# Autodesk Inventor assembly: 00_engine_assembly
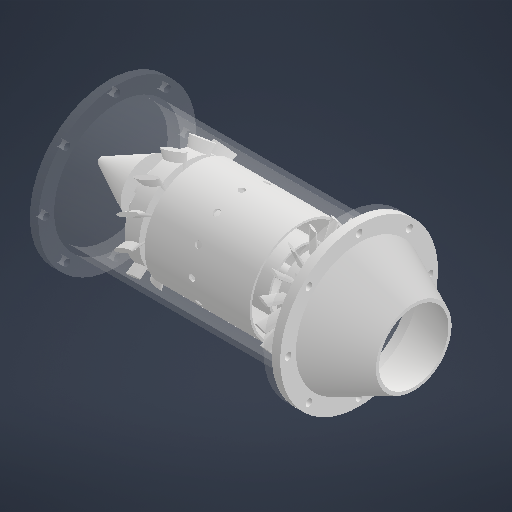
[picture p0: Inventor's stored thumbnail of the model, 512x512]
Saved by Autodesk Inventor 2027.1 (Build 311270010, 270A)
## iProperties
Created: 2026-10
Part Number: 00_engine_assembly
Document SubType Name: Assembly
Designer: BHAVAN KUMAR
Author: BHAVAN KUMAR
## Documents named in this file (8)
- C:\Users\BHAVAN KUMAR\OneDrive\00_engine_assembly.iam
- C:\Users\BHAVAN KUMAR\OneDrive\01_casing.ipt
- C:\Users\BHAVAN KUMAR\OneDrive\02_shaft.ipt
- C:\Users\BHAVAN KUMAR\OneDrive\07_nose_cone.ipt
- C:\Users\BHAVAN KUMAR\OneDrive\03_compressor_rotor.ipt
- C:\Users\BHAVAN KUMAR\OneDrive\04_combustor_liner.ipt
- C:\Users\BHAVAN KUMAR\OneDrive\05_turbine_rotor.ipt
- C:\Users\BHAVAN KUMAR\OneDrive\06_nozzle.ipt
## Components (7 placed, 7 different names)
1. 01_casing:1 — Mate:1, Mate:3, Mate:4, Insert:2
2. 02_shaft:1 — Mate:1, Flush:1, Mate:5
3. 07_nose_cone:1 — Mate:5
4. 03_compressor_rotor:1 — Mate:2, Flush:2
5. 04_combustor_liner:1 — Mate:4, Flush:4
6. 05_turbine_rotor:1 — Mate:3, Flush:3
7. 06_nozzle:1 — Insert:2
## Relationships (10: Mate 5, Flush 4, Insert 1)
- Mate:1: 01_casing:1 ↔ 02_shaft:1
- Flush:1: 02_shaft:1
- Mate:2: 03_compressor_rotor:1
- Flush:2: 03_compressor_rotor:1
- Mate:3: 01_casing:1 ↔ 05_turbine_rotor:1
- Flush:3: 05_turbine_rotor:1
- Mate:4: 01_casing:1 ↔ 04_combustor_liner:1
- Flush:4: 04_combustor_liner:1
- Insert:2: 01_casing:1 ↔ 06_nozzle:1
- Mate:5: 02_shaft:1 ↔ 07_nose_cone:1
